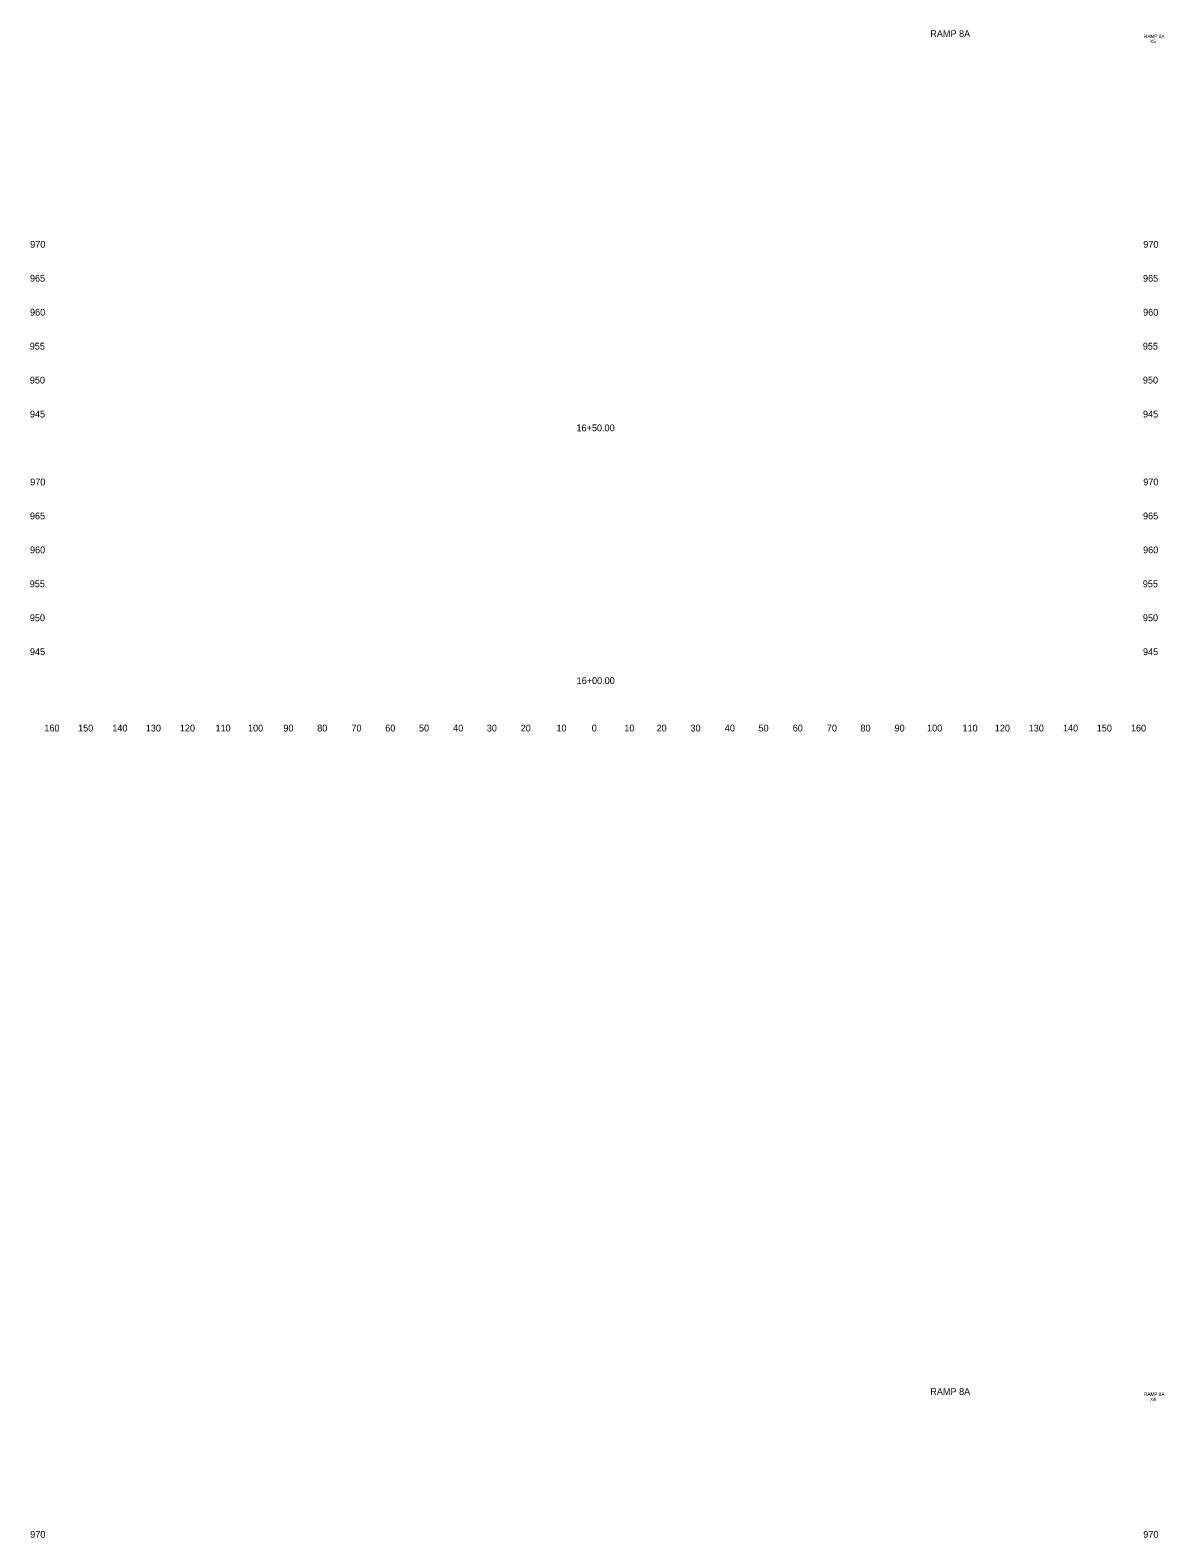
# Model space of a CAD drawing. Extents: x 4994 to 5328, y 4997 to 8804.
# Drawn here: x 4993.9 to 5327.8, y 6360 to 6804.1 of the extents above; entities that cross this region are included whole.
import ezdxf

# ---------------------------------------------------------------- set-up
doc = ezdxf.new("R2010")
doc.units = 0
for name, color, linetype in [('RD_SHT_ID', 7, 'Continuous'), ('RD_XS_TX_Offset', 7, 'Continuous'), ('RD_XS_TX_Station', 7, 'Continuous')]:
    doc.layers.add(name, color=color, linetype=linetype)

msp = doc.modelspace()

# ---------------------------------------------------------------- texts
at = {"layer": 'RD_SHT_ID'}
for s, height, p in [('RAMP 8A', 2, (5259.02, 6802.06)), ('RAMP 8A', 1, (5321.93, 6801.8)), ('X5', 1, (5323.74, 6800.3)), ('RAMP 8A', 2, (5259.02, 6402.06)), ('RAMP 8A', 1, (5321.93, 6401.8)), ('X4', 1, (5323.74, 6400.3))]:
    msp.add_text(s, height=height, dxfattribs=at).set_placement(p)
at = {"layer": 'RD_XS_TX_Offset'}
for s, p in [('970', (4993.94, 6740)), ('970', (5321.74, 6740)), ('965', (4993.86, 6730)), ('965', (5321.66, 6730)), ('960', (4993.89, 6720)), ('960', (5321.69, 6720)), ('955', (4993.8, 6710)), ('955', (5321.6, 6710)), ('950', (4993.83, 6700)), ('950', (5321.63, 6700)), ('945', (4993.86, 6690)), ('945', (5321.66, 6690)), ('970', (4993.94, 6670)), ('970', (5321.74, 6670)), ('965', (4993.86, 6660)), ('965', (5321.66, 6660)), ('960', (4993.89, 6650)), ('960', (5321.69, 6650)), ('955', (4993.8, 6640)), ('955', (5321.6, 6640)), ('950', (4993.83, 6630)), ('950', (5321.63, 6630)), ('945', (4993.86, 6620)), ('945', (5321.66, 6620)), ('160', (4998.1, 6597.5)), ('150', (5008.04, 6597.5)), ('140', (5018.1, 6597.5)), ('130', (5027.99, 6597.5)), ('120', (5038.01, 6597.5)), ('110', (5048.51, 6597.5)), ('100', (5058.07, 6597.5)), ('90', (5068.5, 6597.5)), ('80', (5078.46, 6597.5)), ('70', (5088.54, 6597.5)), ('60', (5098.5, 6597.5)), ('50', (5108.43, 6597.5)), ('40', (5118.5, 6597.5)), ('30', (5128.39, 6597.5)), ('20', (5138.4, 6597.5)), ('10', (5148.91, 6597.5)), ('0', (5159.3, 6597.5)), ('0', (5159.3, 6597.5)), ('10', (5168.91, 6597.5)), ('20', (5178.4, 6597.5)), ('30', (5188.39, 6597.5)), ('40', (5198.5, 6597.5)), ('50', (5208.43, 6597.5)), ('60', (5218.5, 6597.5)), ('70', (5228.54, 6597.5)), ('80', (5238.46, 6597.5)), ('90', (5248.5, 6597.5)), ('100', (5258.07, 6597.5)), ('110', (5268.51, 6597.5)), ('120', (5278.01, 6597.5)), ('130', (5287.99, 6597.5)), ('140', (5298.1, 6597.5)), ('150', (5308.04, 6597.5)), ('160', (5318.1, 6597.5)), ('970', (4993.94, 6360)), ('970', (5321.74, 6360))]:
    msp.add_text(s, height=2, dxfattribs=at).set_placement(p)
at = {"layer": 'RD_XS_TX_Station'}
for s, p in [('16+50.00', (5154.83, 6685.94)), ('16+00.00', (5154.86, 6611.47))]:
    msp.add_text(s, height=2, dxfattribs=at).set_placement(p)

doc.saveas('drawing.dxf')
